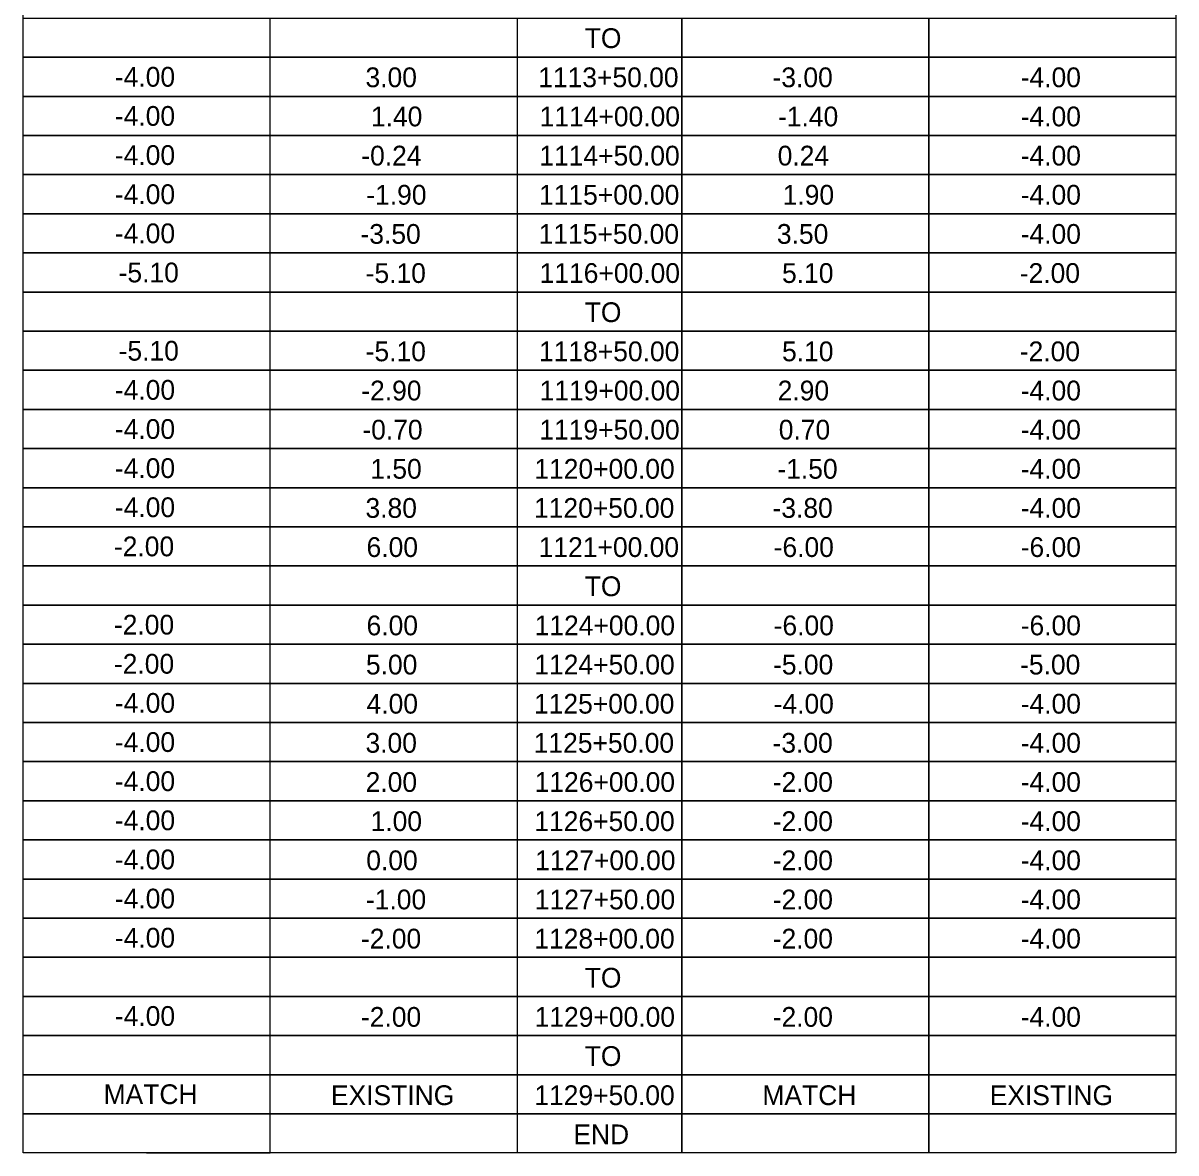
# Model space of a CAD drawing. Extents: x 1026502 to 1027102, y 781811 to 782040.
# Drawn here: x 1027074.42 to 1027102.42, y 781866.07 to 781893.51 of the extents above; entities that cross this region are included whole.
import ezdxf

# ---------------------------------------------------------------- set-up
doc = ezdxf.new("R2010")
doc.units = 0
for name, color, linetype in [('ANNOTATION', 7, 'Continuous'), ('BORDER', 7, 'Continuous'), ('DIMENSIONS', 7, 'Continuous')]:
    doc.layers.add(name, color=color, linetype=linetype)

msp = doc.modelspace()

# ---------------------------------------------------------------- linework, layer by layer
at = {"layer": 'ANNOTATION'}
msp.add_lwpolyline([(1027074.415, 781920.244), (1027102.415, 781920.244), (1027102.415, 781866.071), (1027074.415, 781866.071)], close=True, dxfattribs=at)
at = {"layer": 'BORDER'}
for p, q in [((1027077.415, 781892.682), (1027074.415, 781892.682)), ((1027077.415, 781892.682), (1027074.415, 781892.682)), ((1027077.415, 781892.682), (1027080.415, 781892.682)), ((1027077.415, 781891.732), (1027074.415, 781891.732)), ((1027077.415, 781891.732), (1027074.415, 781891.732)), ((1027077.415, 781891.732), (1027080.415, 781891.732)), ((1027077.415, 781890.781), (1027074.415, 781890.781)), ((1027077.415, 781890.781), (1027074.415, 781890.781)), ((1027077.415, 781890.781), (1027080.415, 781890.781)), ((1027077.415, 781889.831), (1027074.415, 781889.831)), ((1027077.415, 781889.831), (1027074.415, 781889.831)), ((1027077.415, 781889.831), (1027080.415, 781889.831)), ((1027077.415, 781888.881), (1027074.415, 781888.881)), ((1027077.415, 781888.881), (1027074.415, 781888.881)), ((1027077.415, 781888.881), (1027080.415, 781888.881)), ((1027077.415, 781887.93), (1027074.415, 781887.93)), ((1027077.415, 781887.93), (1027074.415, 781887.93)), ((1027077.415, 781887.93), (1027080.415, 781887.93)), ((1027077.415, 781886.98), (1027074.415, 781886.98)), ((1027077.415, 781886.98), (1027074.415, 781886.98)), ((1027077.415, 781886.98), (1027080.415, 781886.98)), ((1027077.415, 781886.029), (1027074.415, 781886.029)), ((1027077.415, 781886.029), (1027074.415, 781886.029)), ((1027077.415, 781886.029), (1027080.415, 781886.029)), ((1027077.415, 781885.079), (1027074.415, 781885.079)), ((1027077.415, 781885.079), (1027074.415, 781885.079)), ((1027077.415, 781885.079), (1027080.415, 781885.079)), ((1027077.415, 781884.129), (1027074.415, 781884.129)), ((1027077.415, 781884.129), (1027074.415, 781884.129)), ((1027077.415, 781884.129), (1027080.415, 781884.129)), ((1027077.415, 781883.178), (1027074.415, 781883.178)), ((1027077.415, 781883.178), (1027074.415, 781883.178)), ((1027077.415, 781883.178), (1027080.415, 781883.178)), ((1027077.415, 781882.228), (1027074.415, 781882.228)), ((1027077.415, 781882.228), (1027074.415, 781882.228)), ((1027077.415, 781882.228), (1027080.415, 781882.228)), ((1027077.415, 781881.277), (1027074.415, 781881.277)), ((1027077.415, 781881.277), (1027074.415, 781881.277)), ((1027077.415, 781881.277), (1027080.415, 781881.277)), ((1027077.415, 781880.327), (1027074.415, 781880.327)), ((1027077.415, 781880.327), (1027074.415, 781880.327)), ((1027077.415, 781880.327), (1027080.415, 781880.327)), ((1027077.415, 781879.377), (1027074.415, 781879.377)), ((1027077.415, 781879.377), (1027074.415, 781879.377)), ((1027077.415, 781879.377), (1027080.415, 781879.377)), ((1027077.415, 781878.426), (1027074.415, 781878.426)), ((1027077.415, 781878.426), (1027074.415, 781878.426)), ((1027077.415, 781878.426), (1027080.415, 781878.426)), ((1027077.415, 781877.476), (1027074.415, 781877.476)), ((1027077.415, 781877.476), (1027074.415, 781877.476)), ((1027077.415, 781877.476), (1027080.415, 781877.476)), ((1027077.415, 781876.525), (1027074.415, 781876.525)), ((1027077.415, 781876.525), (1027074.415, 781876.525)), ((1027077.415, 781876.525), (1027080.415, 781876.525)), ((1027077.415, 781875.575), (1027074.415, 781875.575)), ((1027077.415, 781875.575), (1027074.415, 781875.575)), ((1027077.415, 781875.575), (1027080.415, 781875.575)), ((1027077.415, 781874.625), (1027074.415, 781874.625)), ((1027077.415, 781874.625), (1027074.415, 781874.625)), ((1027077.415, 781874.625), (1027080.415, 781874.625)), ((1027077.415, 781873.674), (1027074.415, 781873.674)), ((1027077.415, 781873.674), (1027074.415, 781873.674)), ((1027077.415, 781873.674), (1027080.415, 781873.674)), ((1027077.415, 781872.724), (1027074.415, 781872.724)), ((1027077.415, 781872.724), (1027074.415, 781872.724)), ((1027077.415, 781872.724), (1027080.415, 781872.724)), ((1027077.415, 781871.773), (1027074.415, 781871.773)), ((1027077.415, 781871.773), (1027074.415, 781871.773)), ((1027077.415, 781871.773), (1027080.415, 781871.773)), ((1027077.415, 781870.823), (1027074.415, 781870.823)), ((1027077.415, 781870.823), (1027074.415, 781870.823)), ((1027077.415, 781870.823), (1027080.415, 781870.823)), ((1027077.415, 781869.873), (1027074.415, 781869.873)), ((1027077.415, 781869.873), (1027074.415, 781869.873)), ((1027077.415, 781869.873), (1027080.415, 781869.873)), ((1027077.415, 781868.922), (1027074.415, 781868.922)), ((1027077.415, 781868.922), (1027074.415, 781868.922)), ((1027077.415, 781868.922), (1027080.415, 781868.922)), ((1027077.415, 781867.972), (1027074.415, 781867.972)), ((1027077.415, 781867.972), (1027074.415, 781867.972)), ((1027077.415, 781867.972), (1027080.415, 781867.972)), ((1027077.415, 781867.021), (1027074.415, 781867.021)), ((1027077.415, 781867.021), (1027074.415, 781867.021)), ((1027077.415, 781867.021), (1027080.415, 781867.021)), ((1027077.415, 781866.071), (1027074.415, 781866.071)), ((1027077.415, 781866.071), (1027074.415, 781866.071)), ((1027077.415, 781866.071), (1027080.415, 781866.071))]:
    msp.add_line(p, q, dxfattribs=at)
for points in [[(1027074.415, 781893.633), (1027102.415, 781893.633), (1027102.415, 781892.682), (1027074.415, 781892.682)], [(1027074.415, 781892.682), (1027102.415, 781892.682), (1027102.415, 781891.732), (1027074.415, 781891.732)], [(1027074.415, 781891.732), (1027102.415, 781891.732), (1027102.415, 781890.781), (1027074.415, 781890.781)], [(1027074.415, 781890.781), (1027102.415, 781890.781), (1027102.415, 781889.831), (1027074.415, 781889.831)], [(1027074.415, 781889.831), (1027102.415, 781889.831), (1027102.415, 781888.881), (1027074.415, 781888.881)], [(1027074.415, 781888.881), (1027102.415, 781888.881), (1027102.415, 781887.93), (1027074.415, 781887.93)], [(1027074.415, 781887.93), (1027102.415, 781887.93), (1027102.415, 781886.98), (1027074.415, 781886.98)], [(1027074.415, 781886.98), (1027102.415, 781886.98), (1027102.415, 781886.029), (1027074.415, 781886.029)], [(1027074.415, 781886.029), (1027102.415, 781886.029), (1027102.415, 781885.079), (1027074.415, 781885.079)], [(1027074.415, 781885.079), (1027102.415, 781885.079), (1027102.415, 781884.129), (1027074.415, 781884.129)], [(1027074.415, 781884.129), (1027102.415, 781884.129), (1027102.415, 781883.178), (1027074.415, 781883.178)], [(1027074.415, 781883.178), (1027102.415, 781883.178), (1027102.415, 781882.228), (1027074.415, 781882.228)], [(1027074.415, 781882.228), (1027102.415, 781882.228), (1027102.415, 781881.277), (1027074.415, 781881.277)], [(1027074.415, 781881.277), (1027102.415, 781881.277), (1027102.415, 781880.327), (1027074.415, 781880.327)], [(1027074.415, 781880.327), (1027102.415, 781880.327), (1027102.415, 781879.377), (1027074.415, 781879.377)], [(1027074.415, 781879.377), (1027102.415, 781879.377), (1027102.415, 781878.426), (1027074.415, 781878.426)], [(1027074.415, 781878.426), (1027102.415, 781878.426), (1027102.415, 781877.476), (1027074.415, 781877.476)], [(1027074.415, 781877.476), (1027102.415, 781877.476), (1027102.415, 781876.525), (1027074.415, 781876.525)], [(1027074.415, 781876.525), (1027102.415, 781876.525), (1027102.415, 781875.575), (1027074.415, 781875.575)], [(1027074.415, 781875.575), (1027102.415, 781875.575), (1027102.415, 781874.625), (1027074.415, 781874.625)], [(1027074.415, 781874.625), (1027102.415, 781874.625), (1027102.415, 781873.674), (1027074.415, 781873.674)], [(1027074.415, 781873.674), (1027102.415, 781873.674), (1027102.415, 781872.724), (1027074.415, 781872.724)], [(1027074.415, 781872.724), (1027102.415, 781872.724), (1027102.415, 781871.773), (1027074.415, 781871.773)], [(1027074.415, 781871.773), (1027102.415, 781871.773), (1027102.415, 781870.823), (1027074.415, 781870.823)], [(1027074.415, 781870.823), (1027102.415, 781870.823), (1027102.415, 781869.873), (1027074.415, 781869.873)], [(1027074.415, 781869.873), (1027102.415, 781869.873), (1027102.415, 781868.922), (1027074.415, 781868.922)], [(1027074.415, 781868.922), (1027102.415, 781868.922), (1027102.415, 781867.972), (1027074.415, 781867.972)], [(1027074.415, 781867.972), (1027102.415, 781867.972), (1027102.415, 781867.021), (1027074.415, 781867.021)], [(1027074.415, 781867.021), (1027102.415, 781867.021), (1027102.415, 781866.071), (1027074.415, 781866.071)]]:
    msp.add_lwpolyline(points, close=True, dxfattribs=at)
for points in [[(1027086.415, 781893.633), (1027086.415, 781892.682), (1027080.415, 781892.682), (1027080.415, 781893.633)], [(1027090.415, 781893.633), (1027090.415, 781892.682), (1027086.415, 781892.682)], [(1027096.415, 781893.633), (1027096.415, 781892.682), (1027090.415, 781892.682), (1027090.415, 781893.633)], [(1027102.415, 781893.633), (1027102.415, 781892.682), (1027096.415, 781892.682), (1027096.415, 781893.633)], [(1027086.415, 781892.682), (1027086.415, 781891.732), (1027080.415, 781891.732), (1027080.415, 781892.682)], [(1027090.415, 781892.682), (1027090.415, 781891.732), (1027086.415, 781891.732)], [(1027096.415, 781892.682), (1027096.415, 781891.732), (1027090.415, 781891.732), (1027090.415, 781892.682)], [(1027102.415, 781892.682), (1027102.415, 781891.732), (1027096.415, 781891.732), (1027096.415, 781892.682)], [(1027086.415, 781891.732), (1027086.415, 781890.781), (1027080.415, 781890.781), (1027080.415, 781891.732)], [(1027090.415, 781891.732), (1027090.415, 781890.781), (1027086.415, 781890.781)], [(1027096.415, 781891.732), (1027096.415, 781890.781), (1027090.415, 781890.781), (1027090.415, 781891.732)], [(1027102.415, 781891.732), (1027102.415, 781890.781), (1027096.415, 781890.781), (1027096.415, 781891.732)], [(1027086.415, 781890.781), (1027086.415, 781889.831), (1027080.415, 781889.831), (1027080.415, 781890.781)], [(1027090.415, 781890.781), (1027090.415, 781889.831), (1027086.415, 781889.831)], [(1027096.415, 781890.781), (1027096.415, 781889.831), (1027090.415, 781889.831), (1027090.415, 781890.781)], [(1027102.415, 781890.781), (1027102.415, 781889.831), (1027096.415, 781889.831), (1027096.415, 781890.781)], [(1027086.415, 781889.831), (1027086.415, 781888.881), (1027080.415, 781888.881), (1027080.415, 781889.831)], [(1027090.415, 781889.831), (1027090.415, 781888.881), (1027086.415, 781888.881)], [(1027096.415, 781889.831), (1027096.415, 781888.881), (1027090.415, 781888.881), (1027090.415, 781889.831)], [(1027102.415, 781889.831), (1027102.415, 781888.881), (1027096.415, 781888.881), (1027096.415, 781889.831)], [(1027086.415, 781888.881), (1027086.415, 781887.93), (1027080.415, 781887.93), (1027080.415, 781888.881)], [(1027090.415, 781888.881), (1027090.415, 781887.93), (1027086.415, 781887.93)], [(1027096.415, 781888.881), (1027096.415, 781887.93), (1027090.415, 781887.93), (1027090.415, 781888.881)], [(1027102.415, 781888.881), (1027102.415, 781887.93), (1027096.415, 781887.93), (1027096.415, 781888.881)], [(1027086.415, 781887.93), (1027086.415, 781886.98), (1027080.415, 781886.98), (1027080.415, 781887.93)], [(1027090.415, 781887.93), (1027090.415, 781886.98), (1027086.415, 781886.98)], [(1027096.415, 781887.93), (1027096.415, 781886.98), (1027090.415, 781886.98), (1027090.415, 781887.93)], [(1027102.415, 781887.93), (1027102.415, 781886.98), (1027096.415, 781886.98), (1027096.415, 781887.93)], [(1027086.415, 781886.98), (1027086.415, 781886.029), (1027080.415, 781886.029), (1027080.415, 781886.98)], [(1027090.415, 781886.98), (1027090.415, 781886.029), (1027086.415, 781886.029)], [(1027096.415, 781886.98), (1027096.415, 781886.029), (1027090.415, 781886.029), (1027090.415, 781886.98)], [(1027102.415, 781886.98), (1027102.415, 781886.029), (1027096.415, 781886.029), (1027096.415, 781886.98)], [(1027086.415, 781886.029), (1027086.415, 781885.079), (1027080.415, 781885.079), (1027080.415, 781886.029)], [(1027090.415, 781886.029), (1027090.415, 781885.079), (1027086.415, 781885.079)], [(1027096.415, 781886.029), (1027096.415, 781885.079), (1027090.415, 781885.079), (1027090.415, 781886.029)], [(1027102.415, 781886.029), (1027102.415, 781885.079), (1027096.415, 781885.079), (1027096.415, 781886.029)], [(1027086.415, 781885.079), (1027086.415, 781884.129), (1027080.415, 781884.129), (1027080.415, 781885.079)], [(1027090.415, 781885.079), (1027090.415, 781884.129), (1027086.415, 781884.129)], [(1027096.415, 781885.079), (1027096.415, 781884.129), (1027090.415, 781884.129), (1027090.415, 781885.079)], [(1027102.415, 781885.079), (1027102.415, 781884.129), (1027096.415, 781884.129), (1027096.415, 781885.079)], [(1027086.415, 781884.129), (1027086.415, 781883.178), (1027080.415, 781883.178), (1027080.415, 781884.129)], [(1027090.415, 781884.129), (1027090.415, 781883.178), (1027086.415, 781883.178)], [(1027096.415, 781884.129), (1027096.415, 781883.178), (1027090.415, 781883.178), (1027090.415, 781884.129)], [(1027102.415, 781884.129), (1027102.415, 781883.178), (1027096.415, 781883.178), (1027096.415, 781884.129)], [(1027086.415, 781883.178), (1027086.415, 781882.228), (1027080.415, 781882.228), (1027080.415, 781883.178)], [(1027090.415, 781883.178), (1027090.415, 781882.228), (1027086.415, 781882.228)], [(1027096.415, 781883.178), (1027096.415, 781882.228), (1027090.415, 781882.228), (1027090.415, 781883.178)], [(1027102.415, 781883.178), (1027102.415, 781882.228), (1027096.415, 781882.228), (1027096.415, 781883.178)], [(1027086.415, 781882.228), (1027086.415, 781881.277), (1027080.415, 781881.277), (1027080.415, 781882.228)], [(1027090.415, 781882.228), (1027090.415, 781881.277), (1027086.415, 781881.277)], [(1027096.415, 781882.228), (1027096.415, 781881.277), (1027090.415, 781881.277), (1027090.415, 781882.228)], [(1027102.415, 781882.228), (1027102.415, 781881.277), (1027096.415, 781881.277), (1027096.415, 781882.228)], [(1027086.415, 781881.277), (1027086.415, 781880.327), (1027080.415, 781880.327), (1027080.415, 781881.277)], [(1027090.415, 781881.277), (1027090.415, 781880.327), (1027086.415, 781880.327)], [(1027096.415, 781881.277), (1027096.415, 781880.327), (1027090.415, 781880.327), (1027090.415, 781881.277)], [(1027102.415, 781881.277), (1027102.415, 781880.327), (1027096.415, 781880.327), (1027096.415, 781881.277)], [(1027086.415, 781880.327), (1027086.415, 781879.377), (1027080.415, 781879.377), (1027080.415, 781880.327)], [(1027090.415, 781880.327), (1027090.415, 781879.377), (1027086.415, 781879.377)], [(1027096.415, 781880.327), (1027096.415, 781879.377), (1027090.415, 781879.377), (1027090.415, 781880.327)], [(1027102.415, 781880.327), (1027102.415, 781879.377), (1027096.415, 781879.377), (1027096.415, 781880.327)], [(1027086.415, 781879.377), (1027086.415, 781878.426), (1027080.415, 781878.426), (1027080.415, 781879.377)], [(1027090.415, 781879.377), (1027090.415, 781878.426), (1027086.415, 781878.426)], [(1027096.415, 781879.377), (1027096.415, 781878.426), (1027090.415, 781878.426), (1027090.415, 781879.377)], [(1027102.415, 781879.377), (1027102.415, 781878.426), (1027096.415, 781878.426), (1027096.415, 781879.377)], [(1027086.415, 781878.426), (1027086.415, 781877.476), (1027080.415, 781877.476), (1027080.415, 781878.426)], [(1027090.415, 781878.426), (1027090.415, 781877.476), (1027086.415, 781877.476)], [(1027096.415, 781878.426), (1027096.415, 781877.476), (1027090.415, 781877.476), (1027090.415, 781878.426)], [(1027102.415, 781878.426), (1027102.415, 781877.476), (1027096.415, 781877.476), (1027096.415, 781878.426)], [(1027086.415, 781877.476), (1027086.415, 781876.525), (1027080.415, 781876.525), (1027080.415, 781877.476)], [(1027090.415, 781877.476), (1027090.415, 781876.525), (1027086.415, 781876.525)], [(1027096.415, 781877.476), (1027096.415, 781876.525), (1027090.415, 781876.525), (1027090.415, 781877.476)], [(1027102.415, 781877.476), (1027102.415, 781876.525), (1027096.415, 781876.525), (1027096.415, 781877.476)], [(1027086.415, 781876.525), (1027086.415, 781875.575), (1027080.415, 781875.575), (1027080.415, 781876.525)], [(1027090.415, 781876.525), (1027090.415, 781875.575), (1027086.415, 781875.575)], [(1027096.415, 781876.525), (1027096.415, 781875.575), (1027090.415, 781875.575), (1027090.415, 781876.525)], [(1027102.415, 781876.525), (1027102.415, 781875.575), (1027096.415, 781875.575), (1027096.415, 781876.525)], [(1027086.415, 781875.575), (1027086.415, 781874.625), (1027080.415, 781874.625), (1027080.415, 781875.575)], [(1027090.415, 781875.575), (1027090.415, 781874.625), (1027086.415, 781874.625)], [(1027096.415, 781875.575), (1027096.415, 781874.625), (1027090.415, 781874.625), (1027090.415, 781875.575)], [(1027102.415, 781875.575), (1027102.415, 781874.625), (1027096.415, 781874.625), (1027096.415, 781875.575)], [(1027086.415, 781874.625), (1027086.415, 781873.674), (1027080.415, 781873.674), (1027080.415, 781874.625)], [(1027090.415, 781874.625), (1027090.415, 781873.674), (1027086.415, 781873.674)], [(1027096.415, 781874.625), (1027096.415, 781873.674), (1027090.415, 781873.674), (1027090.415, 781874.625)], [(1027102.415, 781874.625), (1027102.415, 781873.674), (1027096.415, 781873.674), (1027096.415, 781874.625)], [(1027086.415, 781873.674), (1027086.415, 781872.724), (1027080.415, 781872.724), (1027080.415, 781873.674)], [(1027090.415, 781873.674), (1027090.415, 781872.724), (1027086.415, 781872.724)], [(1027096.415, 781873.674), (1027096.415, 781872.724), (1027090.415, 781872.724), (1027090.415, 781873.674)], [(1027102.415, 781873.674), (1027102.415, 781872.724), (1027096.415, 781872.724), (1027096.415, 781873.674)], [(1027086.415, 781872.724), (1027086.415, 781871.773), (1027080.415, 781871.773), (1027080.415, 781872.724)], [(1027090.415, 781872.724), (1027090.415, 781871.773), (1027086.415, 781871.773)], [(1027096.415, 781872.724), (1027096.415, 781871.773), (1027090.415, 781871.773), (1027090.415, 781872.724)], [(1027102.415, 781872.724), (1027102.415, 781871.773), (1027096.415, 781871.773), (1027096.415, 781872.724)], [(1027086.415, 781871.773), (1027086.415, 781870.823), (1027080.415, 781870.823), (1027080.415, 781871.773)], [(1027090.415, 781871.773), (1027090.415, 781870.823), (1027086.415, 781870.823)], [(1027096.415, 781871.773), (1027096.415, 781870.823), (1027090.415, 781870.823), (1027090.415, 781871.773)], [(1027102.415, 781871.773), (1027102.415, 781870.823), (1027096.415, 781870.823), (1027096.415, 781871.773)], [(1027086.415, 781870.823), (1027086.415, 781869.873), (1027080.415, 781869.873), (1027080.415, 781870.823)], [(1027090.415, 781870.823), (1027090.415, 781869.873), (1027086.415, 781869.873)], [(1027096.415, 781870.823), (1027096.415, 781869.873), (1027090.415, 781869.873), (1027090.415, 781870.823)], [(1027102.415, 781870.823), (1027102.415, 781869.873), (1027096.415, 781869.873), (1027096.415, 781870.823)], [(1027086.415, 781869.873), (1027086.415, 781868.922), (1027080.415, 781868.922), (1027080.415, 781869.873)], [(1027090.415, 781869.873), (1027090.415, 781868.922), (1027086.415, 781868.922)], [(1027096.415, 781869.873), (1027096.415, 781868.922), (1027090.415, 781868.922), (1027090.415, 781869.873)], [(1027102.415, 781869.873), (1027102.415, 781868.922), (1027096.415, 781868.922), (1027096.415, 781869.873)], [(1027086.415, 781868.922), (1027086.415, 781867.972), (1027080.415, 781867.972), (1027080.415, 781868.922)], [(1027090.415, 781868.922), (1027090.415, 781867.972), (1027086.415, 781867.972)], [(1027096.415, 781868.922), (1027096.415, 781867.972), (1027090.415, 781867.972), (1027090.415, 781868.922)], [(1027102.415, 781868.922), (1027102.415, 781867.972), (1027096.415, 781867.972), (1027096.415, 781868.922)], [(1027086.415, 781867.972), (1027086.415, 781867.021), (1027080.415, 781867.021), (1027080.415, 781867.972)], [(1027090.415, 781867.972), (1027090.415, 781867.021), (1027086.415, 781867.021)], [(1027096.415, 781867.972), (1027096.415, 781867.021), (1027090.415, 781867.021), (1027090.415, 781867.972)], [(1027102.415, 781867.972), (1027102.415, 781867.021), (1027096.415, 781867.021), (1027096.415, 781867.972)], [(1027086.415, 781867.021), (1027086.415, 781866.071), (1027080.415, 781866.071), (1027080.415, 781867.021)], [(1027090.415, 781867.021), (1027090.415, 781866.071), (1027086.415, 781866.071)], [(1027096.415, 781867.021), (1027096.415, 781866.071), (1027090.415, 781866.071), (1027090.415, 781867.021)], [(1027102.415, 781867.021), (1027102.415, 781866.071), (1027096.415, 781866.071), (1027096.415, 781867.021)]]:
    msp.add_lwpolyline(points, dxfattribs=at)

# ---------------------------------------------------------------- texts
at = {"layer": 'DIMENSIONS'}
for s, p in [('TO', (1027088.057, 781892.906)), ('-4.00', (1027076.645, 781891.967)), ('3.00', (1027082.732, 781891.955)), ('1113+50.00', (1027086.927, 781891.955)), ('-3.00', (1027092.618, 781891.955)), ('-4.00', (1027098.645, 781891.955)), ('-4.00', (1027076.645, 781891.017)), ('1.40', (1027082.864, 781891.004)), ('1114+00.00', (1027086.961, 781891.004)), ('-1.40', (1027092.751, 781891.004)), ('-4.00', (1027098.645, 781891.004)), ('-4.00', (1027076.645, 781890.066)), ('-0.24', (1027082.63, 781890.053)), ('1114+50.00', (1027086.954, 781890.053)), ('0.24', (1027092.743, 781890.053)), ('-4.00', (1027098.645, 781890.053)), ('-4.00', (1027076.645, 781889.116)), ('-1.90', (1027082.751, 781889.102)), ('1115+00.00', (1027086.946, 781889.102)), ('1.90', (1027092.864, 781889.102)), ('-4.00', (1027098.645, 781889.102)), ('-4.00', (1027076.645, 781888.165)), ('-3.50', (1027082.611, 781888.151)), ('1115+50.00', (1027086.938, 781888.151)), ('3.50', (1027092.724, 781888.151)), ('-4.00', (1027098.645, 781888.151)), ('-5.10', (1027076.736, 781887.215)), ('-5.10', (1027082.736, 781887.201)), ('1116+00.00', (1027086.961, 781887.201)), ('5.10', (1027092.849, 781887.201)), ('-2.00', (1027098.622, 781887.201)), ('TO', (1027088.057, 781886.25)), ('-5.10', (1027076.736, 781885.314)), ('-5.10', (1027082.736, 781885.299)), ('1118+50.00', (1027086.946, 781885.299)), ('5.10', (1027092.849, 781885.299)), ('-2.00', (1027098.622, 781885.299)), ('-4.00', (1027076.645, 781884.364)), ('-2.90', (1027082.63, 781884.348)), ('1119+00.00', (1027086.961, 781884.348)), ('2.90', (1027092.743, 781884.348)), ('-4.00', (1027098.645, 781884.348)), ('-4.00', (1027076.645, 781883.413)), ('-0.70', (1027082.656, 781883.397)), ('1119+50.00', (1027086.954, 781883.397)), ('0.70', (1027092.769, 781883.397)), ('-4.00', (1027098.645, 781883.397)), ('-4.00', (1027076.645, 781882.463)), ('1.50', (1027082.849, 781882.446)), ('1120+00.00', (1027086.833, 781882.446)), ('-1.50', (1027092.736, 781882.446)), ('-4.00', (1027098.645, 781882.446)), ('-4.00', (1027076.645, 781881.513)), ('3.80', (1027082.732, 781881.496)), ('1120+50.00', (1027086.825, 781881.496)), ('-3.80', (1027092.618, 781881.496)), ('-4.00', (1027098.645, 781881.496)), ('-2.00', (1027076.622, 781880.562)), ('6.00', (1027082.758, 781880.545)), ('1121+00.00', (1027086.939, 781880.545)), ('-6.00', (1027092.645, 781880.545)), ('-6.00', (1027098.645, 781880.545)), ('TO', (1027088.057, 781879.594)), ('-2.00', (1027076.622, 781878.661)), ('6.00', (1027082.758, 781878.643)), ('1124+00.00', (1027086.84, 781878.643)), ('-6.00', (1027092.645, 781878.643)), ('-6.00', (1027098.645, 781878.643)), ('-2.00', (1027076.622, 781877.711)), ('5.00', (1027082.743, 781877.692)), ('1124+50.00', (1027086.833, 781877.692)), ('-5.00', (1027092.63, 781877.692)), ('-5.00', (1027098.63, 781877.692)), ('-4.00', (1027076.645, 781876.761)), ('4.00', (1027082.758, 781876.741)), ('1125+00.00', (1027086.825, 781876.741)), ('-4.00', (1027092.645, 781876.741)), ('-4.00', (1027098.645, 781876.741)), ('-4.00', (1027076.645, 781875.81)), ('3.00', (1027082.732, 781875.791)), ('1125+50.00', (1027086.818, 781875.791)), ('-3.00', (1027092.618, 781875.791)), ('-4.00', (1027098.645, 781875.791)), ('-4.00', (1027076.645, 781874.86)), ('2.00', (1027082.736, 781874.84)), ('1126+00.00', (1027086.84, 781874.84)), ('-2.00', (1027092.622, 781874.84)), ('-4.00', (1027098.645, 781874.84)), ('-4.00', (1027076.645, 781873.909)), ('1.00', (1027082.856, 781873.889)), ('1126+50.00', (1027086.833, 781873.889)), ('-2.00', (1027092.622, 781873.889)), ('-4.00', (1027098.645, 781873.889)), ('-4.00', (1027076.645, 781872.959)), ('0.00', (1027082.751, 781872.938)), ('1127+00.00', (1027086.852, 781872.938)), ('-2.00', (1027092.622, 781872.938)), ('-4.00', (1027098.645, 781872.938)), ('-4.00', (1027076.645, 781872.009)), ('-1.00', (1027082.743, 781871.987)), ('1127+50.00', (1027086.844, 781871.987)), ('-2.00', (1027092.622, 781871.987)), ('-4.00', (1027098.645, 781871.987)), ('-4.00', (1027076.645, 781871.058)), ('-2.00', (1027082.622, 781871.036)), ('1128+00.00', (1027086.833, 781871.036)), ('-2.00', (1027092.622, 781871.036)), ('-4.00', (1027098.645, 781871.036)), ('TO', (1027088.057, 781870.086)), ('-4.00', (1027076.645, 781869.157)), ('-2.00', (1027082.622, 781869.135)), ('1129+00.00', (1027086.84, 781869.135)), ('-2.00', (1027092.622, 781869.135)), ('-4.00', (1027098.645, 781869.135)), ('TO', (1027088.057, 781868.184)), ('MATCH', (1027076.372, 781867.257)), ('EXISTING', (1027081.892, 781867.233)), ('1129+50.00', (1027086.833, 781867.233)), ('MATCH', (1027092.372, 781867.233)), ('EXISTING', (1027097.892, 781867.233)), ('END', (1027087.78, 781866.282))]:
    msp.add_text(s, height=0.48, dxfattribs=at).set_placement(p)

doc.saveas('drawing.dxf')
